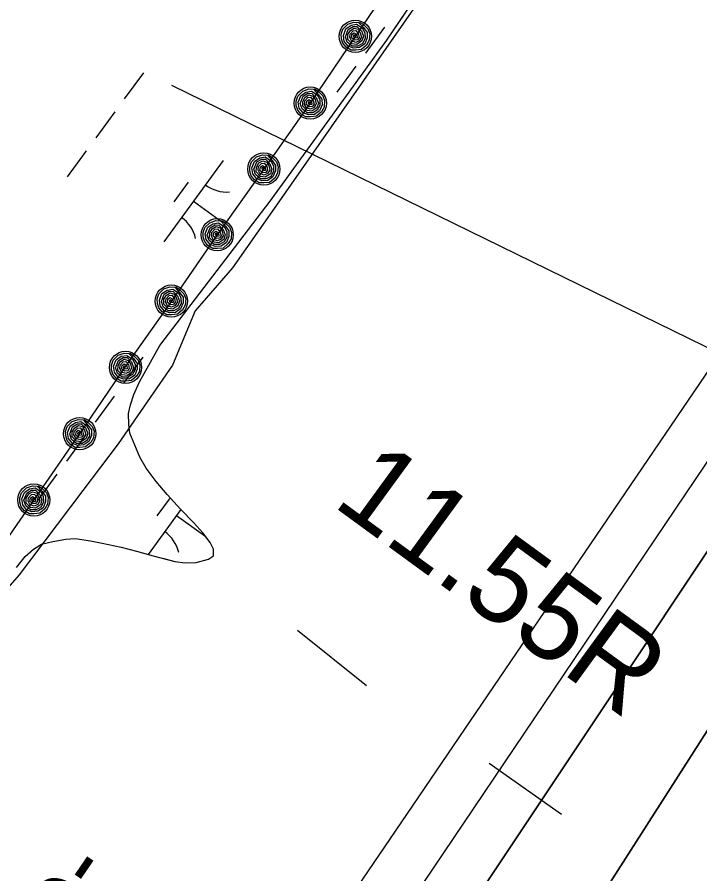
# Model space of a CAD drawing. Extents: x 3905714 to 3926767, y 183354 to 205755.
# Drawn here: x 3914278.4 to 3914617.2, y 190819.7 to 191244.9 of the extents above; entities that cross this region are included whole.
import ezdxf

# ---------------------------------------------------------------- set-up
doc = ezdxf.new("R2010")
doc.units = 0
for name, color, linetype in [('V-LEVE-TOET', 7, 'Continuous'), ('V-RIVR-EDGE', 7, 'Continuous'), ('V-RIVR-RANG', 7, 'Continuous'), ('V-RRAP-FSHR', 7, 'Continuous'), ('V-STRM-FMON', 7, 'Continuous'), ('V-TOPO-DPTH', 7, 'Continuous'), ('V-TOPO-MINR', 7, 'Continuous'), ('V-TOPO-SHOR', 7, 'Continuous'), ('V-UTIL-LINE', 7, 'Continuous'), ('V-WETL-SWMP', 7, 'Continuous')]:
    doc.layers.add(name, color=color, linetype=linetype)

msp = doc.modelspace()

# ---------------------------------------------------------------- linework, layer by layer
at = {"layer": 'V-LEVE-TOET'}
for p, q in [((3914417.53, 190940.6), (3914451.71, 190913.18)), ((3914512.7, 190874.69), (3914548.54, 190849.35))]:
    msp.add_line(p, q, dxfattribs=at)
at = {"layer": 'V-RIVR-EDGE'}
msp.add_lwpolyline([(3914715.15, 191597.23), (3914646.39, 191501.52), (3914626.87, 191460.63), (3914626.87, 191440.19), (3914625.02, 191422.54), (3914592.49, 191407.67), (3914578.56, 191393.73), (3914554.4, 191369.57), (3914494.93, 191277.58), (3914409.44, 191154.92), (3914385.28, 191120.54), (3914366.7, 191099.17), (3914355.55, 191072.22), (3914328.6, 191033.2), (3914310.94, 191009.97), (3914279.35, 190968.15), (3914273.77, 190961.65), (3914253.33, 190939.35), (3914229.17, 190913.33), (3914186.43, 190847.36), (3914165.99, 190817.62)], dxfattribs=at)
at = {"layer": 'V-RRAP-FSHR'}
for points in [[(3914647.42, 191533.88), (3914624.96, 191500.78), (3914602.64, 191467.59), (3914580.32, 191434.39), (3914558.1, 191401.2), (3914535.68, 191368.3), (3914513.36, 191334.81), (3914491.13, 191301.64), (3914468.62, 191268.49), (3914446.23, 191235.34), (3914423.84, 191202.2), (3914400.81, 191169.5), (3914377.67, 191136.87), (3914354.92, 191103.97), (3914332.17, 191071.71), (3914309.41, 191038.17), (3914286.66, 191005.27), (3914263.91, 190972.37), (3914241.16, 190939.47), (3914218.41, 190906.57), (3914195.66, 190873.67), (3914172.18, 190841.3), (3914148.13, 190809.34)], [(3914448.31, 191242.37), (3914450.09, 191241.3), (3914452.43, 191239.02), (3914453.34, 191236.6), (3914453.12, 191233.39), (3914451.75, 191231), (3914449.27, 191228.79), (3914446.38, 191228.49), (3914444.11, 191228.47), (3914441.67, 191229.93), (3914440.06, 191231.88), (3914439.31, 191234.11), (3914439.21, 191236.33), (3914440.04, 191238.81), (3914442.46, 191241.3), (3914445.46, 191242.38), (3914447.86, 191242.28), (3914450.24, 191239.69), (3914452.02, 191237.31), (3914452.08, 191234.52), (3914450.87, 191231.53), (3914448.33, 191229.75), (3914445.32, 191229.48), (3914442.71, 191230.47), (3914440.75, 191232.85), (3914440.27, 191235.79), (3914441.54, 191238.99), (3914444.08, 191240.81), (3914446.82, 191241.32), (3914449.66, 191239.51), (3914450.94, 191237.06), (3914451.06, 191234.22), (3914449.74, 191231.79), (3914447.45, 191230.48), (3914444.69, 191230.48), (3914442.24, 191232.45), (3914441.3, 191235.13), (3914442.66, 191238.77), (3914445.1, 191240.23), (3914447, 191240.18), (3914449.21, 191238.05), (3914450.25, 191235.37), (3914449.52, 191233.04), (3914447.04, 191231.29), (3914444.7, 191231.64), (3914442.47, 191233.78), (3914442.51, 191236.19), (3914443.75, 191238.28), (3914445.59, 191239.4), (3914447.58, 191238.83), (3914448.62, 191237.14), (3914449.24, 191234.92), (3914448.18, 191233.13), (3914446.4, 191232.32), (3914444.32, 191233.02), (3914443.41, 191234.7), (3914443.57, 191236.46), (3914445.07, 191238.09), (3914446.39, 191238.22), (3914447.7, 191236.71), (3914448.12, 191234.83), (3914447.34, 191233.62), (3914445.79, 191233.51), (3914444.28, 191234.63), (3914444.5, 191236.26), (3914445.51, 191237.13), (3914446.93, 191236.31), (3914447.1, 191234.67), (3914445.95, 191234.43), (3914445.32, 191235.38), (3914445.61, 191236.18), (3914446.27, 191235.38)], [(3914425.92, 191209.22), (3914427.7, 191208.15), (3914430.04, 191205.87), (3914430.95, 191203.45), (3914430.73, 191200.25), (3914429.36, 191197.86), (3914426.88, 191195.65), (3914423.99, 191195.34), (3914421.72, 191195.32), (3914419.28, 191196.79), (3914417.66, 191198.73), (3914416.92, 191200.97), (3914416.82, 191203.18), (3914417.65, 191205.66), (3914420.08, 191208.15), (3914423.07, 191209.24), (3914425.47, 191209.13), (3914427.85, 191206.54), (3914429.63, 191204.17), (3914429.69, 191201.38), (3914428.48, 191198.38), (3914425.94, 191196.6), (3914422.93, 191196.34), (3914420.32, 191197.33), (3914418.36, 191199.71), (3914417.88, 191202.65), (3914419.15, 191205.85), (3914421.69, 191207.66), (3914424.43, 191208.18), (3914427.27, 191206.36), (3914428.54, 191203.91), (3914428.67, 191201.07), (3914427.35, 191198.65), (3914425.06, 191197.34), (3914422.3, 191197.33), (3914419.85, 191199.3), (3914418.91, 191201.98), (3914420.27, 191205.62), (3914422.71, 191207.08), (3914424.61, 191207.03), (3914426.81, 191204.91), (3914427.86, 191202.22), (3914427.13, 191199.89), (3914424.65, 191198.14), (3914422.31, 191198.49), (3914420.08, 191200.63), (3914420.12, 191203.04), (3914421.35, 191205.13), (3914423.2, 191206.25), (3914425.19, 191205.69), (3914426.23, 191203.99), (3914426.85, 191201.77), (3914425.79, 191199.99), (3914424, 191199.18), (3914421.93, 191199.87), (3914421.02, 191201.55), (3914421.18, 191203.31), (3914422.68, 191204.95), (3914424, 191205.08), (3914425.31, 191203.56), (3914425.73, 191201.68), (3914424.95, 191200.48), (3914423.4, 191200.37), (3914421.89, 191201.49), (3914422.1, 191203.11), (3914423.12, 191203.98), (3914424.54, 191203.16), (3914424.71, 191201.53), (3914423.56, 191201.28), (3914422.93, 191202.24), (3914423.22, 191203.03), (3914423.88, 191202.23)], [(3914403.06, 191176.47), (3914404.81, 191175.36), (3914407.1, 191173.02), (3914407.95, 191170.58), (3914407.65, 191167.38), (3914406.22, 191165.02), (3914403.69, 191162.87), (3914400.79, 191162.64), (3914398.52, 191162.67), (3914396.12, 191164.2), (3914394.55, 191166.18), (3914393.86, 191168.43), (3914393.82, 191170.65), (3914394.7, 191173.11), (3914397.19, 191175.54), (3914400.21, 191176.55), (3914402.61, 191176.39), (3914404.92, 191173.74), (3914406.65, 191171.32), (3914406.64, 191168.53), (3914405.35, 191165.57), (3914402.77, 191163.85), (3914399.76, 191163.66), (3914397.17, 191164.71), (3914395.27, 191167.14), (3914394.86, 191170.09), (3914396.21, 191173.26), (3914398.79, 191175.01), (3914401.55, 191175.46), (3914404.34, 191173.58), (3914405.55, 191171.1), (3914405.61, 191168.25), (3914404.23, 191165.86), (3914401.91, 191164.61), (3914399.15, 191164.67), (3914396.75, 191166.7), (3914395.87, 191169.4), (3914397.32, 191173), (3914399.79, 191174.41), (3914401.7, 191174.31), (3914403.85, 191172.13), (3914404.83, 191169.42), (3914404.04, 191167.11), (3914401.52, 191165.42), (3914399.18, 191165.83), (3914397.01, 191168.02), (3914397.11, 191170.43), (3914398.4, 191172.49), (3914400.27, 191173.56), (3914402.24, 191172.95), (3914403.25, 191171.23), (3914403.81, 191169), (3914402.7, 191167.24), (3914400.9, 191166.47), (3914398.84, 191167.22), (3914397.97, 191168.92), (3914398.18, 191170.67), (3914399.71, 191172.27), (3914401.04, 191172.37), (3914402.31, 191170.82), (3914402.69, 191168.94), (3914401.88, 191167.75), (3914400.32, 191167.68), (3914398.84, 191168.83), (3914399.1, 191170.45), (3914400.13, 191171.3), (3914401.53, 191170.44), (3914401.66, 191168.8), (3914400.5, 191168.59), (3914399.9, 191169.56), (3914400.21, 191170.34), (3914400.85, 191169.53)], [(3914379.82, 191143.87), (3914381.6, 191142.78), (3914383.91, 191140.47), (3914384.8, 191138.05), (3914384.54, 191134.84), (3914383.14, 191132.46), (3914380.64, 191130.28), (3914377.75, 191130.01), (3914375.47, 191130.02), (3914373.06, 191131.51), (3914371.46, 191133.47), (3914370.73, 191135.71), (3914370.67, 191137.93), (3914371.52, 191140.4), (3914373.97, 191142.86), (3914376.98, 191143.92), (3914379.38, 191143.79), (3914381.73, 191141.17), (3914383.49, 191138.77), (3914383.51, 191135.98), (3914382.27, 191133), (3914379.71, 191131.25), (3914376.7, 191131.02), (3914374.1, 191132.04), (3914372.16, 191134.44), (3914371.71, 191137.38), (3914373.02, 191140.57), (3914375.58, 191142.36), (3914378.33, 191142.84), (3914381.15, 191141), (3914382.39, 191138.53), (3914382.49, 191135.69), (3914381.14, 191133.28), (3914378.83, 191131.99), (3914376.08, 191132.02), (3914373.65, 191134.02), (3914372.74, 191136.71), (3914374.14, 191140.33), (3914376.59, 191141.76), (3914378.5, 191141.69), (3914380.68, 191139.54), (3914381.69, 191136.85), (3914380.94, 191134.52), (3914378.43, 191132.8), (3914376.1, 191133.18), (3914373.89, 191135.34), (3914373.96, 191137.75), (3914375.22, 191139.83), (3914377.08, 191140.93), (3914379.06, 191140.34), (3914380.08, 191138.64), (3914380.68, 191136.41), (3914379.59, 191134.64), (3914377.8, 191133.85), (3914375.74, 191134.56), (3914374.84, 191136.25), (3914375.02, 191138.01), (3914376.54, 191139.63), (3914377.86, 191139.75), (3914379.15, 191138.21), (3914379.56, 191136.33), (3914378.77, 191135.14), (3914377.21, 191135.04), (3914375.71, 191136.18), (3914375.95, 191137.8), (3914376.97, 191138.66), (3914378.38, 191137.82), (3914378.53, 191136.19), (3914377.38, 191135.96), (3914376.76, 191136.92), (3914377.06, 191137.71), (3914377.71, 191136.9)], [(3914357.07, 191110.97), (3914358.85, 191109.88), (3914361.16, 191107.57), (3914362.04, 191105.15), (3914361.79, 191101.94), (3914360.39, 191099.57), (3914357.89, 191097.39), (3914354.99, 191097.11), (3914352.72, 191097.12), (3914350.3, 191098.61), (3914348.71, 191100.57), (3914347.98, 191102.81), (3914347.91, 191105.03), (3914348.77, 191107.5), (3914351.22, 191109.96), (3914354.22, 191111.02), (3914356.62, 191110.89), (3914358.97, 191108.27), (3914360.73, 191105.88), (3914360.76, 191103.08), (3914359.52, 191100.1), (3914356.95, 191098.35), (3914353.95, 191098.12), (3914351.34, 191099.14), (3914349.41, 191101.54), (3914348.96, 191104.49), (3914350.27, 191107.67), (3914352.83, 191109.46), (3914355.58, 191109.94), (3914358.39, 191108.1), (3914359.64, 191105.63), (3914359.74, 191102.79), (3914358.39, 191100.38), (3914356.08, 191099.1), (3914353.32, 191099.12), (3914350.9, 191101.12), (3914349.98, 191103.81), (3914351.39, 191107.43), (3914353.84, 191108.86), (3914355.74, 191108.79), (3914357.92, 191106.64), (3914358.94, 191103.95), (3914358.19, 191101.62), (3914355.68, 191099.91), (3914353.34, 191100.28), (3914351.14, 191102.44), (3914351.2, 191104.85), (3914352.46, 191106.93), (3914354.33, 191108.03), (3914356.31, 191107.44), (3914357.33, 191105.74), (3914357.93, 191103.51), (3914356.84, 191101.74), (3914355.05, 191100.95), (3914352.98, 191101.67), (3914352.09, 191103.35), (3914352.27, 191105.11), (3914353.79, 191106.73), (3914355.11, 191106.85), (3914356.4, 191105.32), (3914356.8, 191103.43), (3914356.01, 191102.24), (3914354.45, 191102.14), (3914352.96, 191103.28), (3914353.19, 191104.9), (3914354.21, 191105.76), (3914355.63, 191104.92), (3914355.78, 191103.29), (3914354.62, 191103.06), (3914354.01, 191104.02), (3914354.3, 191104.81), (3914354.96, 191104)], [(3914334.32, 191078.07), (3914336.09, 191076.99), (3914338.41, 191074.67), (3914339.29, 191072.25), (3914339.03, 191069.05), (3914337.64, 191066.67), (3914335.13, 191064.49), (3914332.24, 191064.21), (3914329.97, 191064.22), (3914327.55, 191065.71), (3914325.95, 191067.67), (3914325.23, 191069.91), (3914325.16, 191072.13), (3914326.01, 191074.6), (3914328.47, 191077.07), (3914331.47, 191078.12), (3914333.87, 191077.99), (3914336.22, 191075.37), (3914337.98, 191072.98), (3914338.01, 191070.18), (3914336.76, 191067.2), (3914334.2, 191065.45), (3914331.19, 191065.22), (3914328.59, 191066.24), (3914326.66, 191068.64), (3914326.21, 191071.59), (3914327.52, 191074.77), (3914330.07, 191076.56), (3914332.82, 191077.04), (3914335.64, 191075.2), (3914336.89, 191072.74), (3914336.99, 191069.89), (3914335.64, 191067.48), (3914333.33, 191066.2), (3914330.57, 191066.22), (3914328.14, 191068.22), (3914327.23, 191070.91), (3914328.63, 191074.53), (3914331.08, 191075.97), (3914332.99, 191075.89), (3914335.17, 191073.75), (3914336.19, 191071.05), (3914335.43, 191068.73), (3914332.93, 191067.01), (3914330.59, 191067.38), (3914328.39, 191069.55), (3914328.45, 191071.95), (3914329.71, 191074.03), (3914331.57, 191075.13), (3914333.55, 191074.55), (3914334.58, 191072.84), (3914335.17, 191070.61), (3914334.09, 191068.84), (3914332.3, 191068.05), (3914330.23, 191068.77), (3914329.33, 191070.45), (3914329.52, 191072.21), (3914331.03, 191073.83), (3914332.36, 191073.95), (3914333.65, 191072.42), (3914334.05, 191070.54), (3914333.26, 191069.34), (3914331.7, 191069.24), (3914330.21, 191070.38), (3914330.44, 191072), (3914331.46, 191072.86), (3914332.88, 191072.02), (3914333.03, 191070.39), (3914331.87, 191070.16), (3914331.25, 191071.12), (3914331.55, 191071.91), (3914332.2, 191071.1)], [(3914311.57, 191045.17), (3914313.34, 191044.09), (3914315.66, 191041.77), (3914316.54, 191039.35), (3914316.28, 191036.15), (3914314.89, 191033.77), (3914312.38, 191031.59), (3914309.49, 191031.31), (3914307.21, 191031.32), (3914304.8, 191032.81), (3914303.2, 191034.77), (3914302.48, 191037.02), (3914302.41, 191039.23), (3914303.26, 191041.7), (3914305.71, 191044.17), (3914308.72, 191045.22), (3914311.12, 191045.09), (3914313.47, 191042.47), (3914315.23, 191040.08), (3914315.25, 191037.29), (3914314.01, 191034.3), (3914311.45, 191032.55), (3914308.44, 191032.32), (3914305.84, 191033.34), (3914303.91, 191035.74), (3914303.45, 191038.69), (3914304.77, 191041.87), (3914307.32, 191043.66), (3914310.07, 191044.14), (3914312.89, 191042.3), (3914314.14, 191039.84), (3914314.23, 191036.99), (3914312.89, 191034.58), (3914310.58, 191033.3), (3914307.82, 191033.32), (3914305.39, 191035.32), (3914304.48, 191038.01), (3914305.88, 191041.63), (3914308.33, 191043.07), (3914310.24, 191042.99), (3914312.42, 191040.85), (3914313.43, 191038.15), (3914312.68, 191035.83), (3914310.18, 191034.11), (3914307.84, 191034.48), (3914305.63, 191036.65), (3914305.7, 191039.05), (3914306.96, 191041.14), (3914308.82, 191042.23), (3914310.8, 191041.65), (3914311.83, 191039.94), (3914312.42, 191037.71), (3914311.33, 191035.94), (3914309.54, 191035.15), (3914307.48, 191035.87), (3914306.58, 191037.55), (3914306.77, 191039.31), (3914308.28, 191040.93), (3914309.6, 191041.05), (3914310.89, 191039.52), (3914311.3, 191037.64), (3914310.51, 191036.44), (3914308.95, 191036.35), (3914307.46, 191037.48), (3914307.69, 191039.1), (3914308.71, 191039.96), (3914310.12, 191039.13), (3914310.27, 191037.49), (3914309.12, 191037.26), (3914308.5, 191038.22), (3914308.8, 191039.01), (3914309.45, 191038.2)], [(3914288.81, 191012.27), (3914290.59, 191011.19), (3914292.9, 191008.88), (3914293.79, 191006.45), (3914293.53, 191003.25), (3914292.13, 191000.87), (3914289.63, 190998.69), (3914286.73, 190998.41), (3914284.46, 190998.42), (3914282.04, 190999.91), (3914280.45, 191001.87), (3914279.72, 191004.12), (3914279.66, 191006.33), (3914280.51, 191008.8), (3914282.96, 191011.27), (3914285.96, 191012.32), (3914288.37, 191012.19), (3914290.71, 191009.57), (3914292.48, 191007.18), (3914292.5, 191004.39), (3914291.26, 191001.4), (3914288.7, 190999.65), (3914285.69, 190999.42), (3914283.08, 191000.44), (3914281.15, 191002.84), (3914280.7, 191005.79), (3914282.01, 191008.97), (3914284.57, 191010.76), (3914287.32, 191011.24), (3914290.14, 191009.4), (3914291.38, 191006.94), (3914291.48, 191004.1), (3914290.14, 191001.68), (3914287.82, 191000.4), (3914285.06, 191000.42), (3914282.64, 191002.42), (3914281.73, 191005.11), (3914283.13, 191008.73), (3914285.58, 191010.17), (3914287.48, 191010.1), (3914289.67, 191007.95), (3914290.68, 191005.25), (3914289.93, 191002.93), (3914287.42, 191001.21), (3914285.08, 191001.58), (3914282.88, 191003.75), (3914282.95, 191006.16), (3914284.21, 191008.24), (3914286.07, 191009.33), (3914288.05, 191008.75), (3914289.07, 191007.04), (3914289.67, 191004.82), (3914288.58, 191003.04), (3914286.79, 191002.25), (3914284.73, 191002.97), (3914283.83, 191004.66), (3914284.01, 191006.41), (3914285.53, 191008.04), (3914286.85, 191008.15), (3914288.14, 191006.62), (3914288.55, 191004.74), (3914287.76, 191003.54), (3914286.2, 191003.45), (3914284.71, 191004.58), (3914284.94, 191006.2), (3914285.96, 191007.06), (3914287.37, 191006.23), (3914287.52, 191004.59), (3914286.37, 191004.36), (3914285.75, 191005.32), (3914286.05, 191006.11), (3914286.7, 191005.3)]]:
    msp.add_lwpolyline(points, dxfattribs=at)
for centre in [(3914446.23, 191235.34), (3914423.84, 191202.2), (3914400.81, 191169.5), (3914377.67, 191136.87), (3914354.92, 191103.97), (3914332.17, 191071.07), (3914309.41, 191038.17), (3914286.66, 191005.27)]:
    msp.add_circle(centre, 8, dxfattribs=at)
at = {"layer": 'V-TOPO-DPTH'}
for points in [[(3915286.48, 192081.34), (3914909.08, 191498.19), (3914900.28, 191484.59), (3914891.49, 191470.99), (3914882.7, 191457.38), (3914873.92, 191443.77), (3914860.96, 191423.68), (3914858.65, 191420.12), (3914856.34, 191416.56), (3914854.01, 191413.01), (3914851.68, 191409.46), (3914840.17, 191392.03), (3914832.05, 191379.78), (3914823.89, 191367.56), (3914815.69, 191355.37), (3914807.45, 191343.21), (3914466.27, 190841.37), (3914433.28, 190792.74), (3914400.37, 190744.06), (3914367.58, 190695.3), (3914334.85, 190646.5), (3914011.64, 190163.24)], [(3914008.82, 190002.72), (3914466.37, 190645.48), (3914472.14, 190655.97), (3914478.05, 190666.37), (3914484.06, 190676.73), (3914490.79, 190688.15), (3914493.54, 190692.73), (3914496.32, 190697.29), (3914499.17, 190701.81), (3914502.06, 190706.3), (3914517.41, 190729.79), (3914527.99, 190746.02), (3914538.53, 190762.27), (3914549.02, 190778.55), (3914559.48, 190794.86), (3914922.67, 191362.75), (3914924.45, 191365.53), (3914926.23, 191368.31), (3914928.03, 191371.08), (3914929.82, 191373.85), (3915305.59, 191952.33)], [(3914008.82, 190002.72), (3914466.37, 190645.48), (3914472.14, 190655.97), (3914478.05, 190666.37), (3914484.06, 190676.73), (3914490.79, 190688.15), (3914493.54, 190692.73), (3914496.32, 190697.29), (3914499.17, 190701.81), (3914502.06, 190706.3), (3914517.41, 190729.79), (3914527.99, 190746.02), (3914538.53, 190762.27), (3914549.02, 190778.55), (3914559.48, 190794.86), (3914922.67, 191362.75), (3914924.45, 191365.53), (3914926.23, 191368.31), (3914928.03, 191371.08), (3914929.82, 191373.85), (3915305.59, 191952.33)], [(3914152.91, 190258.95), (3914175.19, 190291.69), (3914196.68, 190324.95), (3914217.65, 190358.56), (3914238.36, 190392.34), (3914259.24, 190426.02), (3914280.37, 190459.54), (3914301.68, 190492.95), (3914413.53, 190666.85), (3914430.93, 190693.77), (3914448.43, 190720.62), (3914466.07, 190747.38), (3914483.79, 190774.08), (3914586.79, 190928.4), (3914638.01, 191005.43), (3914689.05, 191082.58), (3914739.81, 191159.91), (3914790.4, 191237.35), (3914863.51, 191349.73), (3914877.39, 191371.08), (3914891.27, 191392.44), (3914905.12, 191413.82), (3914918.97, 191435.19), (3914998.19, 191557.59)], [(3914998.19, 191557.59), (3914918.97, 191435.19), (3914905.12, 191413.82), (3914891.27, 191392.44), (3914877.39, 191371.08), (3914863.51, 191349.73), (3914790.4, 191237.35), (3914739.81, 191159.91), (3914689.05, 191082.58), (3914638.01, 191005.43), (3914586.79, 190928.4), (3914483.79, 190774.08), (3914466.07, 190747.38), (3914448.43, 190720.62), (3914430.93, 190693.77), (3914413.53, 190666.85), (3914301.68, 190492.95), (3914280.37, 190459.54), (3914259.24, 190426.02), (3914238.36, 190392.34), (3914217.65, 190358.56), (3914196.68, 190324.95), (3914175.19, 190291.69), (3914152.91, 190258.95)]]:
    msp.add_lwpolyline(points, dxfattribs=at)
at = {"layer": 'V-TOPO-MINR'}
for points in [[(3915286.48, 192081.34), (3914909.08, 191498.19), (3914900.28, 191484.59), (3914891.49, 191470.99), (3914882.7, 191457.38), (3914873.92, 191443.77), (3914860.96, 191423.68), (3914858.65, 191420.12), (3914856.34, 191416.56), (3914854.01, 191413.01), (3914851.68, 191409.46), (3914840.17, 191392.03), (3914832.05, 191379.78), (3914823.89, 191367.56), (3914815.69, 191355.37), (3914807.45, 191343.21), (3914466.27, 190841.37), (3914433.28, 190792.74), (3914400.37, 190744.06), (3914367.58, 190695.3), (3914334.85, 190646.5), (3914011.64, 190163.24)], [(3915305.59, 191952.33), (3914929.82, 191373.85), (3914928.03, 191371.08), (3914926.23, 191368.31), (3914924.45, 191365.53), (3914922.67, 191362.75), (3914559.48, 190794.86), (3914549.02, 190778.55), (3914538.53, 190762.27), (3914527.99, 190746.02), (3914517.41, 190729.79), (3914502.06, 190706.3), (3914499.17, 190701.81), (3914496.32, 190697.29), (3914493.54, 190692.73), (3914490.79, 190688.15), (3914484.06, 190676.73), (3914478.05, 190666.37), (3914472.14, 190655.97), (3914466.37, 190645.48), (3914008.82, 190002.72)], [(3914998.19, 191557.59), (3914918.97, 191435.19), (3914905.12, 191413.82), (3914891.27, 191392.44), (3914877.39, 191371.08), (3914863.51, 191349.73), (3914790.4, 191237.35), (3914739.81, 191159.91), (3914689.05, 191082.58), (3914638.01, 191005.43), (3914586.79, 190928.4), (3914483.79, 190774.08), (3914466.07, 190747.38), (3914448.43, 190720.62), (3914430.93, 190693.77), (3914413.53, 190666.85), (3914301.68, 190492.95), (3914280.37, 190459.54), (3914259.24, 190426.02), (3914238.36, 190392.34), (3914217.65, 190358.56), (3914196.68, 190324.95), (3914175.19, 190291.69), (3914152.91, 190258.95)], [(3914966.71, 191548.17), (3914935.73, 191500.29), (3914889.95, 191429.45), (3914881.87, 191416.98), (3914873.78, 191404.52), (3914865.67, 191392.07), (3914857.53, 191379.64), (3914816.13, 191316.49), (3914787.2, 191272.54), (3914758.16, 191228.67), (3914728.95, 191184.91), (3914699.63, 191141.22), (3914474.94, 190807.79), (3914449.63, 190770.09), (3914424.4, 190732.34), (3914399.3, 190694.5), (3914374.28, 190656.61), (3914162.04, 190334.02), (3914148.43, 190313.19), (3914134.9, 190292.29), (3914121.52, 190271.31)]]:
    msp.add_lwpolyline(points, dxfattribs=at)
at = {"layer": 'V-TOPO-SHOR'}
msp.add_lwpolyline([(3914278.11, 190971.74), (3914282.41, 190977.16), (3914286.43, 190980.92), (3914290.45, 190983.28), (3914296.13, 190984.68), (3914302.52, 190985.8), (3914307.23, 190986.22), (3914314.87, 190984.99), (3914320.56, 190983.89), (3914330, 190981.82), (3914337.64, 190979.89), (3914345.83, 190977.54), (3914351.24, 190976.16), (3914356.66, 190974.78), (3914361.79, 190974.1), (3914367.21, 190974.25), (3914373.31, 190975.92), (3914375.81, 190977.59), (3914375.8, 190980.78), (3914374.13, 190984.25), (3914370.51, 190988.96), (3914366.06, 190993.95), (3914359.39, 191000.74), (3914352.86, 191007.95), (3914347.3, 191014.46), (3914342.43, 191021.11), (3914339.23, 191026.52), (3914334.35, 191038.45), (3914333.79, 191042.75), (3914333.64, 191048.16), (3914334.61, 191052.46), (3914336.27, 191057.6), (3914339.03, 191063.85), (3914349.13, 191081.91), (3914403.98, 191153.61), (3914461.86, 191233.49), (3914526.1, 191328.24)], dxfattribs=at)
at = {"layer": 'V-UTIL-LINE'}
msp.add_line((3914354.97, 191211.17), (3916411.07, 190203.76), dxfattribs=at)
at = {"layer": 'V-WETL-SWMP'}
for p, q in [((3914461.86, 191233.49), (3914526.11, 191328.24)), ((3914460.64, 191239.92), (3914451.18, 191227.02)), ((3914403.98, 191153.61), (3914461.86, 191233.49)), ((3914446.45, 191220.56), (3914437, 191207.66)), ((3914341.04, 191217.27), (3914331.58, 191204.37)), ((3914326.86, 191197.91), (3914317.4, 191185.01)), ((3914312.67, 191178.55), (3914303.22, 191165.65)), ((3914380.68, 191173.72), (3914351.13, 191133.39)), ((3914363.23, 191162.95), (3914356.14, 191153.27)), ((3914349.13, 191081.91), (3914403.98, 191153.61)), ((3914365.91, 191153.55), (3914380.43, 191142.92)), ((3914339.03, 191063.85), (3914349.13, 191081.91)), ((3914340.69, 191076.21), (3914331.23, 191063.3)), ((3914336.27, 191057.6), (3914339.03, 191063.85)), ((3914326.51, 191056.85), (3914317.05, 191043.94)), ((3914334.61, 191052.46), (3914336.27, 191057.6)), ((3914333.64, 191048.16), (3914334.61, 191052.46)), ((3914333.79, 191042.75), (3914333.64, 191048.16)), ((3914334.35, 191038.45), (3914333.79, 191042.75)), ((3914312.32, 191037.49), (3914302.87, 191024.58)), ((3914339.23, 191026.52), (3914334.35, 191038.45)), ((3914342.43, 191021.11), (3914339.23, 191026.52)), ((3914347.3, 191014.46), (3914342.43, 191021.11)), ((3914298.14, 191018.13), (3914288.68, 191005.22)), ((3914352.86, 191007.95), (3914347.3, 191014.46)), ((3914359.39, 191000.74), (3914352.86, 191007.95)), ((3914354.34, 191006.31), (3914347.78, 190997.35)), ((3914359.64, 191000.49), (3914343.35, 190978.25)), ((3914366.06, 190993.95), (3914359.39, 191000.74)), ((3914357.55, 190997.63), (3914371.96, 190987.07)), ((3914370.51, 190988.96), (3914366.06, 190993.95)), ((3914296.13, 190984.68), (3914302.52, 190985.8)), ((3914302.52, 190985.8), (3914307.23, 190986.22)), ((3914307.23, 190986.22), (3914314.87, 190984.99)), ((3914374.13, 190984.25), (3914370.51, 190988.96)), ((3914286.43, 190980.92), (3914290.45, 190983.28)), ((3914290.45, 190983.28), (3914296.13, 190984.68)), ((3914314.87, 190984.99), (3914320.56, 190983.89)), ((3914320.56, 190983.89), (3914330, 190981.82)), ((3914330, 190981.82), (3914337.64, 190979.89)), ((3914375.8, 190980.78), (3914374.13, 190984.25)), ((3914278.11, 190971.74), (3914282.41, 190977.16)), ((3914282.41, 190977.16), (3914286.43, 190980.92)), ((3914337.64, 190979.89), (3914345.83, 190977.54)), ((3914345.83, 190977.54), (3914356.66, 190974.78)), ((3914373.31, 190975.92), (3914375.8, 190977.59)), ((3914375.8, 190977.59), (3914375.8, 190980.78)), ((3914356.66, 190974.78), (3914361.79, 190974.1)), ((3914361.79, 190974.1), (3914367.21, 190974.24)), ((3914367.21, 190974.24), (3914373.31, 190975.92))]:
    msp.add_line(p, q, dxfattribs=at)
for centre, start, end in [((3914382.42, 191175.69), 233, 274.5436), ((3914349.77, 191131.13), 13, 54.5436), ((3914341.41, 190975.21), 13, 54.5436)]:
    msp.add_arc(centre, 17.62, start, end, dxfattribs=at)

# ---------------------------------------------------------------- texts
at = {"layer": 'V-RIVR-RANG'}
msp.add_text('-6', height=33.5, rotation=235.6483, dxfattribs=at).set_placement((3914305.15, 190836.29))
at = {"layer": 'V-STRM-FMON'}
msp.add_text('11.55R', height=42, rotation=323.8719, dxfattribs=at).set_placement((3914434.18, 191002.9))

doc.saveas('drawing.dxf')
